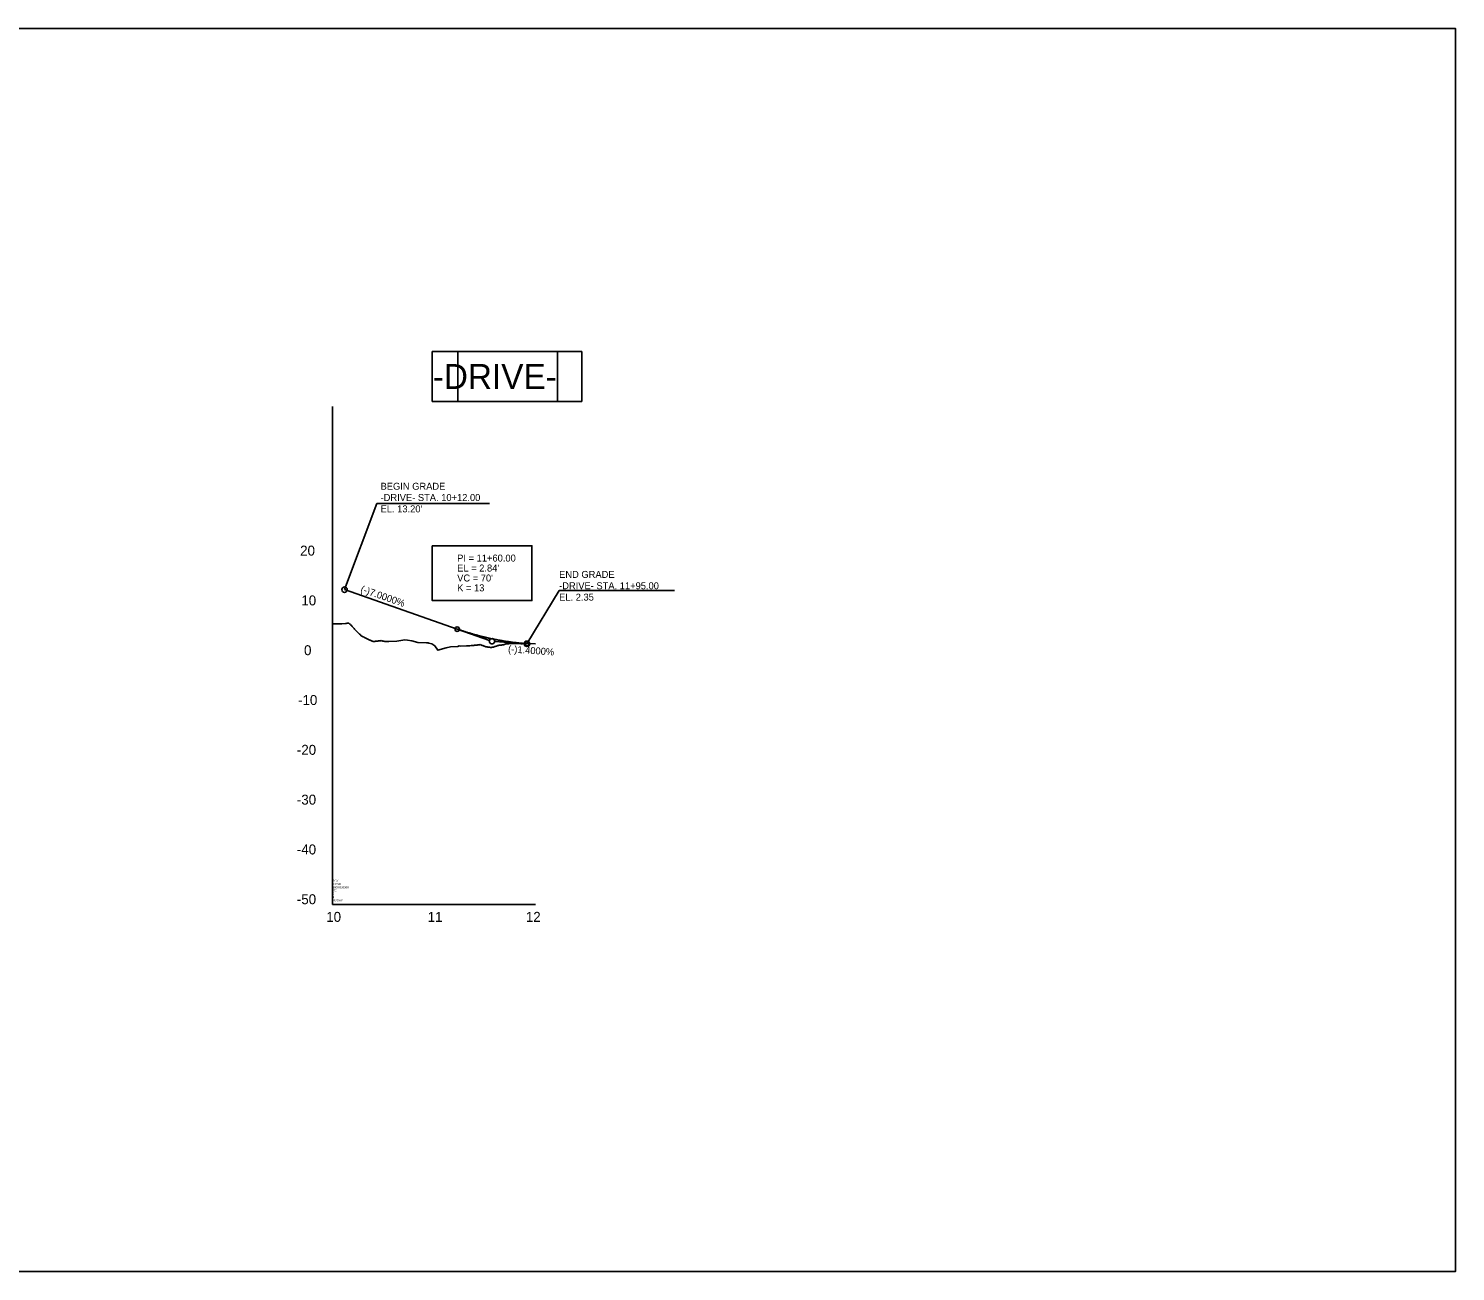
# Model space of a CAD drawing. Extents: x 1626634 to 1638383, y 876896 to 886347.
# Drawn here: x 1628067 to 1629499, y 876896 to 878144 of the extents above; entities that cross this region are included whole.
import ezdxf

# ---------------------------------------------------------------- set-up
doc = ezdxf.new("R2010")
doc.units = 0
for name, color, linetype in [('Exist Profile Cell', 7, 'Continuous'), ('Exist Vertical Profile Ground Line', 7, 'Continuous'), ('Exist Vertical Profile Horizontal Axis Label Major', 7, 'Continuous'), ('Exist Vertical Profile Vertical Axis Label', 7, 'Continuous'), ('Prop Vertical Profile Curve Label', 7, 'Continuous'), ('Prop Vertical Profile Grade', 7, 'Continuous'), ('Prop Vertical Profile Grade Label', 7, 'Continuous'), ('Prop VPI Label', 7, 'Continuous')]:
    doc.layers.add(name, color=color, linetype=linetype)

msp = doc.modelspace()

# ---------------------------------------------------------------- linework, layer by layer
at = {"layer": 'Exist Profile Cell'}
for q in [(1628371.7, 877764.5), (1628575.2, 877264.5), (1628371.7, 877264.5)]:
    msp.add_line((1628371.7, 877264.5), q, dxfattribs=at)
at = {"layer": 'Exist Vertical Profile Ground Line'}
msp.add_lwpolyline([(1628371.7, 877546.3), (1628377.8, 877546.1), (1628380.8, 877546.1), (1628384.6, 877546.5), (1628385.1, 877546.6), (1628385.6, 877546.6), (1628386.1, 877546.7), (1628386.6, 877546.8), (1628387, 877546.8), (1628388, 877546.7), (1628388.5, 877546.3), (1628389, 877545.9), (1628389.5, 877545.4), (1628390, 877545), (1628390.6, 877544.5), (1628390.9, 877544.1), (1628391.4, 877543.5), (1628391.9, 877543), (1628392.4, 877542.5), (1628392.9, 877541.9), (1628393.4, 877541.4), (1628393.8, 877540.9), (1628394.3, 877540.3), (1628394.8, 877539.8), (1628395.3, 877539.3), (1628395.8, 877538.8), (1628396.3, 877538.3), (1628396.7, 877537.7), (1628397.2, 877537.2), (1628397.7, 877536.7), (1628398.7, 877535.7), (1628399.2, 877535.4), (1628399.7, 877535.1), (1628400.1, 877534.6), (1628400.5, 877534.1), (1628401.1, 877533.8), (1628401.6, 877533.5), (1628402.1, 877533.3), (1628402.6, 877533), (1628403.1, 877532.8), (1628403.5, 877532.5), (1628404, 877532.3), (1628404.5, 877532), (1628405, 877531.8), (1628405.5, 877531.6), (1628406, 877531.4), (1628406.5, 877531.1), (1628406.9, 877530.9), (1628407.4, 877530.6), (1628407.9, 877530.4), (1628408.4, 877530.1), (1628408.9, 877529.9), (1628409.4, 877529.7), (1628409.9, 877529.4), (1628410.8, 877529), (1628411.3, 877528.9), (1628411.8, 877528.8), (1628412.3, 877528.6), (1628412.8, 877528.5), (1628413.3, 877528.4), (1628413.7, 877528.5), (1628414.2, 877528.6), (1628414.8, 877528.7), (1628415.2, 877528.8), (1628415.7, 877528.8), (1628416.2, 877528.8), (1628416.7, 877528.9), (1628417.1, 877528.9), (1628417.6, 877529), (1628418.1, 877529), (1628418.6, 877529.1), (1628419.1, 877529.2), (1628419.6, 877529.2), (1628420.5, 877529.3), (1628421, 877529.2), (1628421.5, 877529), (1628422, 877528.9), (1628422.5, 877528.8), (1628423, 877528.8), (1628423.5, 877528.7), (1628423.9, 877528.6), (1628425.8, 877528.3), (1628428.2, 877528.4), (1628436.2, 877528.8), (1628444.2, 877530), (1628446.7, 877529.7), (1628451.1, 877529), (1628457.1, 877527.6), (1628466, 877527.1), (1628467.5, 877527.1), (1628468.4, 877526.9), (1628471.1, 877526.2), (1628474.4, 877524), (1628477.3, 877519.6), (1628485.6, 877522.2), (1628490, 877523.1), (1628497.3, 877523.3), (1628498.8, 877524), (1628500.5, 877523.7), (1628506, 877524), (1628508.5, 877524.1), (1628509.3, 877524.2), (1628510.7, 877524.3), (1628512.3, 877524.5), (1628512.9, 877524.5), (1628513.5, 877524.6), (1628514.2, 877524.7), (1628514.8, 877524.7), (1628515.4, 877524.8), (1628516.1, 877524.9), (1628516.7, 877524.9), (1628517.3, 877525), (1628517.9, 877525.1), (1628518.6, 877525.1), (1628519.2, 877525.2), (1628519.9, 877525.3), (1628520.5, 877525.1), (1628521.1, 877524.8), (1628521.7, 877524.6), (1628522.4, 877524.4), (1628523, 877524.1), (1628523.6, 877523.9), (1628524.2, 877523.7), (1628524.9, 877523.5), (1628525.6, 877523.2), (1628526.1, 877523.1), (1628526.8, 877523), (1628527.4, 877522.9), (1628528, 877522.8), (1628528.6, 877522.7), (1628529.3, 877522.6), (1628529.9, 877522.5), (1628530.5, 877522.4), (1628531, 877522.3), (1628531.8, 877522.6), (1628532.4, 877522.8), (1628533, 877522.9), (1628533.7, 877523.1), (1628534.3, 877523.3), (1628535.2, 877523.5), (1628535.6, 877523.6), (1628536.2, 877523.9), (1628536.8, 877524.1), (1628537.5, 877524.4), (1628538.1, 877524.6), (1628538.7, 877524.7), (1628539.3, 877524.8), (1628540, 877524.8), (1628540.6, 877524.9), (1628541.3, 877524.9), (1628541.9, 877525), (1628542.5, 877525.1), (1628543.1, 877525.2), (1628543.7, 877525.4), (1628544.4, 877525.6), (1628545, 877525.8), (1628545.6, 877526), (1628546.3, 877526.1), (1628546.9, 877526.2), (1628547.5, 877526.2), (1628548.1, 877526.2), (1628548.8, 877526.3), (1628549.4, 877526.3), (1628550, 877526.3), (1628550.7, 877526.3), (1628551.3, 877526.4), (1628551.9, 877526.4), (1628552.6, 877526.4), (1628553.2, 877526.4), (1628553.8, 877526.5), (1628554.4, 877526.5), (1628555.1, 877526.5), (1628555.7, 877526.5), (1628556.5, 877526.6), (1628557, 877526.5), (1628557.6, 877526.5), (1628558.2, 877526.4), (1628558.8, 877526.4), (1628559.5, 877526.3), (1628560.1, 877526.3), (1628560.7, 877526.2), (1628561.4, 877526.2), (1628562.2, 877526.1), (1628569.7, 877526.3), (1628575.2, 877526.2)], dxfattribs=at)
at = {"layer": 'Prop Vertical Profile Curve Label'}
msp.add_lwpolyline([(1626634.5, 878143.8), (1629498.6, 878143.8), (1629498.6, 876896), (1626634.5, 876896)], close=True, dxfattribs=at)
for centre in [(1628496.7, 877540.9), (1628566.7, 877526.2)]:
    msp.add_circle(centre, 2.25, dxfattribs=at)
at = {"layer": 'Prop Vertical Profile Grade'}
msp.add_line((1628383.7, 877580.5), (1628496.7, 877540.9), dxfattribs=at)
msp.add_spline([(1628496.7, 877540.9), (1628498.1, 877540.5), (1628499.5, 877540), (1628500.9, 877539.5), (1628502.3, 877539.1), (1628503.7, 877538.6), (1628505.1, 877538.1), (1628506.5, 877537.7), (1628507.9, 877537.3), (1628509.3, 877536.9), (1628510.7, 877536.4), (1628512.1, 877536), (1628513.5, 877535.6), (1628514.9, 877535.2), (1628516.3, 877534.9), (1628517.7, 877534.5), (1628519.1, 877534.1), (1628520.5, 877533.8), (1628521.9, 877533.4), (1628523.3, 877533.1), (1628524.7, 877532.7), (1628526.1, 877532.4), (1628527.5, 877532.1), (1628528.9, 877531.8), (1628530.3, 877531.4), (1628531.7, 877531.1), (1628533.1, 877530.9), (1628534.5, 877530.6), (1628535.9, 877530.3), (1628537.3, 877530), (1628538.7, 877529.8), (1628540.1, 877529.5), (1628541.5, 877529.3), (1628542.9, 877529), (1628544.3, 877528.8), (1628545.7, 877528.6), (1628547.1, 877528.4), (1628548.5, 877528.2), (1628549.9, 877528), (1628551.3, 877527.8), (1628552.7, 877527.6), (1628554.1, 877527.4), (1628555.5, 877527.3), (1628556.9, 877527.1), (1628558.3, 877527), (1628559.7, 877526.8), (1628561.1, 877526.7), (1628562.5, 877526.6), (1628563.9, 877526.5), (1628565.3, 877526.3), (1628566.7, 877526.2)], degree=3, dxfattribs=at)
at = {"layer": 'Prop VPI Label'}
for p, q in [((1628383.7, 877580.5), (1628415.9, 877666.9)), ((1628529, 877666.9), (1628415.9, 877666.9)), ((1628566.7, 877526.2), (1628599, 877579.6)), ((1628714.9, 877579.6), (1628599, 877579.6)), ((1628496.7, 877540.9), (1628529.1, 877529.6)), ((1628566.7, 877526.2), (1628534.4, 877528.5))]:
    msp.add_line(p, q, dxfattribs=at)
for points in [[(1628471.7, 877819.5), (1628621.7, 877819.5), (1628621.7, 877769.5), (1628471.7, 877769.5)], [(1628471.7, 877819.5), (1628621.7, 877819.5), (1628621.7, 877769.5), (1628471.7, 877769.5)], [(1628497.3, 877819.5), (1628597.3, 877819.5), (1628597.3, 877769.5), (1628497.3, 877769.5)], [(1628497.3, 877819.5), (1628597.3, 877819.5), (1628597.3, 877769.5), (1628497.3, 877769.5)], [(1628471.7, 877624.5), (1628571.7, 877624.5), (1628571.7, 877569.5), (1628471.7, 877569.5)], [(1628471.7, 877624.5), (1628571.7, 877624.5), (1628571.7, 877569.5), (1628471.7, 877569.5)]]:
    msp.add_lwpolyline(points, close=True, dxfattribs=at)
for centre in [(1628383.7, 877580.5), (1628531.7, 877528.7), (1628566.7, 877526.2)]:
    msp.add_circle(centre, 2.75, dxfattribs=at)

# ---------------------------------------------------------------- texts
at = {"layer": 'Exist Profile Cell'}
for s, p in [('RDY', (1628371.7, 877287.2)), ('DRIVE', (1628371.7, 877284)), ('1000.000000', (1628371.7, 877280.7)), ('-50', (1628371.7, 877277.5)), ('5', (1628371.7, 877274.2)), ('1', (1628371.7, 877271)), ('NOGAP', (1628371.7, 877267.7))]:
    msp.add_text(s, height=2, dxfattribs=at).set_placement(p)
at = {"layer": 'Exist Vertical Profile Horizontal Axis Label Major'}
for s, p in [('10', (1628365.3, 877247)), ('11', (1628467.1, 877247)), ('12', (1628565.6, 877247))]:
    msp.add_text(s, height=10, dxfattribs=at).set_placement(p)
at = {"layer": 'Exist Vertical Profile Vertical Axis Label'}
for s, p in [('20', (1628339.1, 877614.7)), ('10', (1628340.3, 877564.7)), ('0', (1628343, 877514.7)), ('-10', (1628337, 877464.7)), ('-20', (1628335.8, 877414.7)), ('-30', (1628335.8, 877364.7)), ('-40', (1628335.8, 877314.7)), ('-50', (1628335.8, 877264.7))]:
    msp.add_text(s, height=10, dxfattribs=at).set_placement(p)
at = {"layer": 'Prop Vertical Profile Curve Label'}
for s, height, p in [('-DRIVE-', 25, (1628472.2, 877782)), ("VC = 70'", 7, (1628496.7, 877588.7)), ('K = 13', 7, (1628496.7, 877578.8))]:
    msp.add_text(s, height=height, dxfattribs=at).set_placement(p)
at = {"layer": 'Prop Vertical Profile Grade Label'}
for s, rotation, p in [('(-)7.0000%', 340.71, (1628399.1, 877578.3)), ('(-)1.4000%', 355.9958, (1628547.6, 877517.6))]:
    msp.add_text(s, height=7, rotation=rotation, dxfattribs=at).set_placement(p)
at = {"layer": 'Prop VPI Label'}
for s, p in [('BEGIN GRADE', (1628419.8, 877680.8)), ('-DRIVE- STA. 10+12.00', (1628419.8, 877669.5)), ("EL. 13.20'", (1628419.8, 877658.1)), ('PI = 11+60.00', (1628496.7, 877608.7)), ("EL = 2.84'", (1628496.7, 877598.7)), ('END GRADE', (1628599, 877592.3)), ('-DRIVE- STA. 11+95.00', (1628599, 877580.9)), ('EL. 2.35', (1628599, 877569.5))]:
    msp.add_text(s, height=7, dxfattribs=at).set_placement(p)

doc.saveas('drawing.dxf')
